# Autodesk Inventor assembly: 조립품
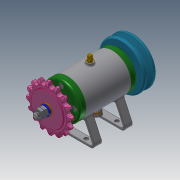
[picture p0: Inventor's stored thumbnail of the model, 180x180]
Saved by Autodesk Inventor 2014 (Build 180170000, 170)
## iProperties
Created: 2021-12
Part Number: 조립품
Document SubType Name: Assembly
Designer: dg
Author: dg
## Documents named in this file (16)
- C:\Users\dg\Desktop\711206v1010\조립품.iam
- C:\Users\dg\Desktop\711206v1010\본체.ipt
- C:\Users\dg\Desktop\711206v1010\V벨트풀리.ipt
- C:\Users\dg\Desktop\711206v1010\너트 M8.ipt
- C:\Users\dg\Desktop\711206v1010\니플 M6 x 0.75.ipt
- C:\Users\dg\Desktop\711206v1010\베어링 6002.ipt
- C:\Users\dg\Desktop\711206v1010\볼트 M4 x 12.ipt
- C:\Users\dg\Desktop\711206v1010\볼트 M6 x 8.ipt
- C:\Users\dg\Desktop\711206v1010\스프로킷.ipt
- C:\Users\dg\Desktop\711206v1010\스프링와셔 8.ipt
- C:\Users\dg\Desktop\711206v1010\오일 실 15 x 25 x 7.ipt
- C:\Users\dg\Desktop\711206v1010\와셔 6 x 11.5.ipt
- C:\Users\dg\Desktop\711206v1010\와셔 8 x 17.ipt
- C:\Users\dg\Desktop\711206v1010\축.ipt
- C:\Users\dg\Desktop\711206v1010\커버.ipt
- C:\Users\dg\Desktop\711206v1010\키 3 x 3.ipt
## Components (11 placed, 3 different names)
1. V벨트풀리:1
2. KS B 2023 6002 - 15 x 32 x 9:1
3. KS B 2023 6002 - 15 x 32 x 9:2
4. ISO 4762 M4 x 12:2
5. ISO 4762 M4 x 12:3
6. ISO 4762 M4 x 12:4
7. ISO 4762 M4 x 12:5
8. ISO 4762 M4 x 12:1
9. ISO 4762 M4 x 12:6
10. ISO 4762 M4 x 12:7
11. ISO 4762 M4 x 12:8
## Named parameters: d3_d0 = 0, d18_d15 = 0, d19_d16 = 0, d20_d17 = 0
